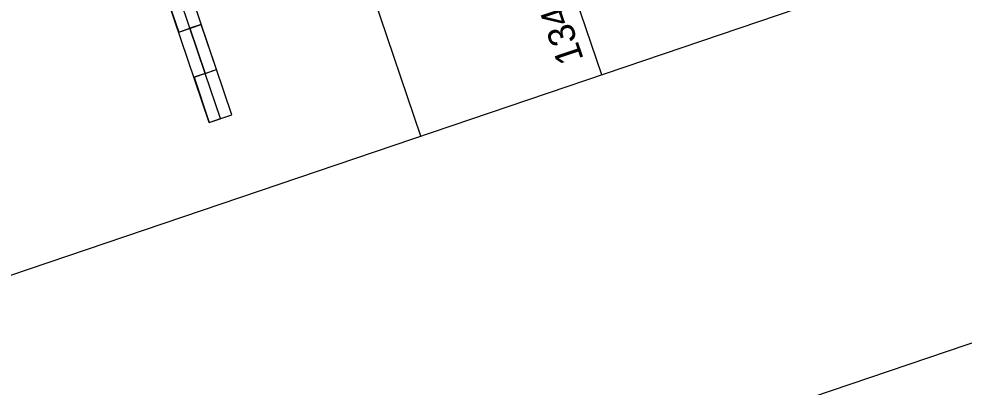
# Model space of a CAD drawing. Extents: x 2150318 to 2152065, y 143281 to 145371.
# Drawn here: x 2151301 to 2151548.2, y 143577.2 to 143673.5 of the extents above; entities that cross this region are included whole.
import ezdxf

# ---------------------------------------------------------------- set-up
doc = ezdxf.new("R2010")
doc.units = 0
for name, color, linetype in [('SHT_Plan_Profile_Sheet_Elev_Txt', 7, 'Continuous'), ('SHT_Plot_Shape_Half', 7, 'Continuous'), ('SHT_Profile_Grid_Major', 7, 'Continuous'), ('SHT_Scale', 7, 'Continuous'), ('SHT_Sheet_Border', 7, 'Continuous')]:
    doc.layers.add(name, color=color, linetype=linetype)

msp = doc.modelspace()

# ---------------------------------------------------------------- linework, layer by layer
at = {"layer": 'SHT_Plot_Shape_Half'}
msp.add_lwpolyline([(2150909.49, 143371.4), (2150363.35, 144981.29), (2151405.04, 145334.68), (2151951.18, 143724.79)], close=True, dxfattribs=at)
at = {"layer": 'SHT_Profile_Grid_Major'}
msp.add_line((2151453.47, 143658.9), (2150947.48, 145150.41), dxfattribs=at)
at = {"layer": 'SHT_Scale'}
for p, q in [((2151356.71, 143648.47), (2151308.64, 143790.17)), ((2151350.79, 143646.46), (2151302.72, 143788.16)), ((2151345.74, 143671.08), (2151341.73, 143682.89)), ((2151345.74, 143671.08), (2151341.73, 143682.89)), ((2151338.78, 143681.88), (2151342.78, 143670.07)), ((2151342.78, 143670.07), (2151348.7, 143672.08)), ((2151342.78, 143670.07), (2151348.7, 143672.08)), ((2151342.78, 143670.07), (2151345.74, 143671.08)), ((2151348.7, 143672.08), (2151345.74, 143671.08)), ((2151349.75, 143659.27), (2151345.74, 143671.08)), ((2151345.74, 143671.08), (2151349.75, 143659.27)), ((2151352.71, 143660.27), (2151348.7, 143672.08)), ((2151346.79, 143658.26), (2151352.71, 143660.27)), ((2151349.75, 143659.27), (2151352.71, 143660.27)), ((2151349.75, 143659.27), (2151346.79, 143658.26)), ((2151346.79, 143658.26), (2151350.79, 143646.46)), ((2151353.75, 143647.46), (2151349.75, 143659.27)), ((2151353.75, 143647.46), (2151349.75, 143659.27)), ((2151350.79, 143646.46), (2151356.71, 143648.47)), ((2151350.79, 143646.46), (2151353.75, 143647.46))]:
    msp.add_line(p, q, dxfattribs=at)
at = {"layer": 'SHT_Sheet_Border'}
msp.add_line((2151406.12, 143642.84), (2150900.13, 145134.35), dxfattribs=at)
msp.add_lwpolyline([(2150901.85, 143471.77), (2150395.86, 144963.28), (2151390.2, 145300.6), (2151896.19, 143809.09)], close=True, dxfattribs=at)

# ---------------------------------------------------------------- texts
at = {"layer": 'SHT_Plan_Profile_Sheet_Elev_Txt'}
msp.add_text('1340', height=7, rotation=108.7393, dxfattribs=at).set_placement((2151448.75, 143662.99))

doc.saveas('drawing.dxf')
